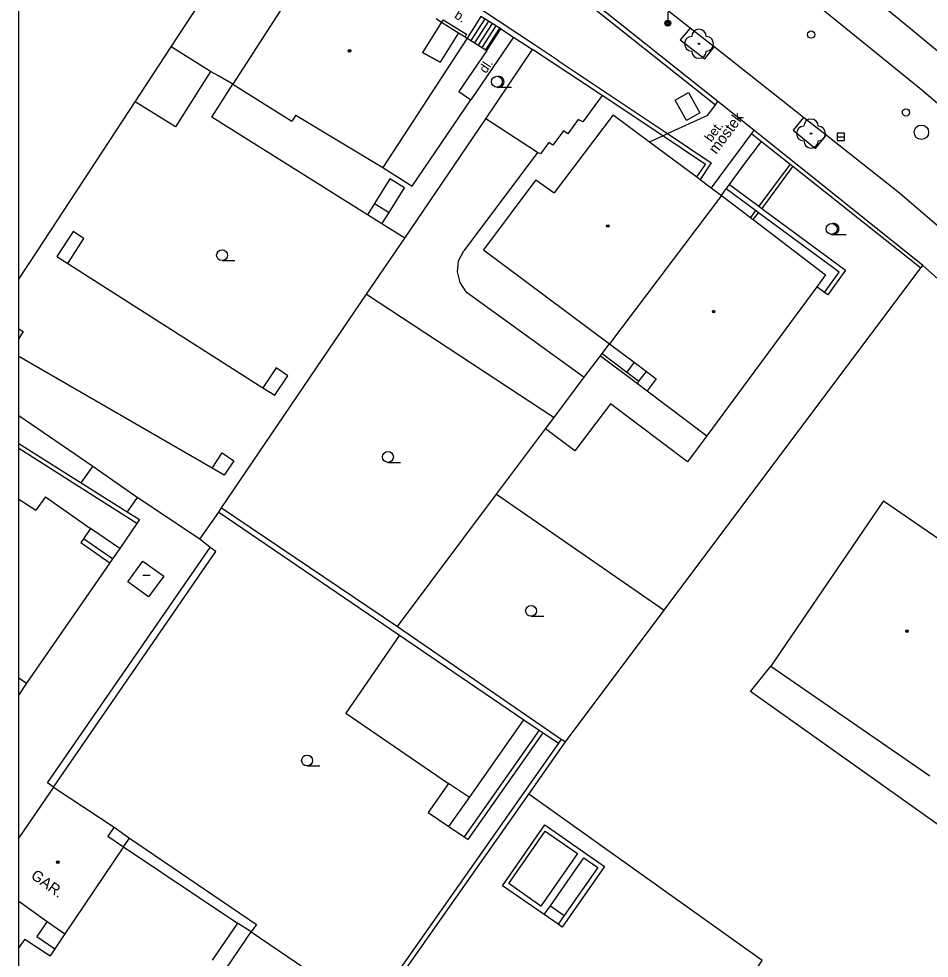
# Model space of a CAD drawing. Extents: x -600309 to -598967, y -1161267 to -1160292.
# Drawn here: x -600308.5 to -600245.8, y -1160468.4 to -1160403.6 of the extents above; entities that cross this region are included whole.
import ezdxf

# ---------------------------------------------------------------- set-up
doc = ezdxf.new("R2010")
doc.units = 0
for name, color, linetype in [('Level 10', 7, 'Continuous'), ('Level 11', 7, 'Continuous'), ('Level 22', 7, 'Continuous'), ('Level 27', 7, 'Continuous'), ('Level 28', 7, 'Continuous'), ('Level 33', 7, 'Continuous'), ('Level 36', 7, 'Continuous'), ('Level 39', 7, 'Continuous'), ('Level 40', 7, 'Continuous'), ('Level 41', 7, 'Continuous'), ('Level 5', 7, 'Continuous'), ('Level 6', 7, 'Continuous'), ('Level 7', 7, 'Continuous'), ('Level 8', 7, 'Continuous'), ('Vrstva 63', 7, 'Continuous')]:
    doc.layers.add(name, color=color, linetype=linetype)

msp = doc.modelspace()

# ---------------------------------------------------------------- linework, layer by layer
at = {"layer": 'Level 10'}
for points in [[(-600130.99, -1160509.15), (-600139.44, -1160503.56), (-600147.26, -1160498.02), (-600154.8, -1160492.15), (-600161.77, -1160486.34), (-600165.04, -1160483.54), (-600170.09, -1160478.96), (-600176.09, -1160473.27), (-600190.6599, -1160459.23), (-600212.67, -1160438.18), (-600221.71, -1160429.76), (-600228.39, -1160423.74), (-600239.15, -1160414.63), (-600244.48, -1160410.12), (-600246.35, -1160408.54), (-600258.81, -1160398.4099), (-600274.98, -1160385.83), (-600282.26, -1160380.2)], [(-600116.15, -1160526.25), (-600126.1, -1160520.21), (-600138.76, -1160511.76), (-600151.84, -1160502.25), (-600159.7, -1160496.34), (-600170.75, -1160487.14), (-600176.1, -1160482.15), (-600185.2199, -1160473.25), (-600195.18, -1160463.81), (-600206.08, -1160453.49), (-600217.54, -1160442.6), (-600229.4099, -1160431.52), (-600247.87, -1160415.6599), (-600252.92, -1160411.68), (-600254.47, -1160410.46), (-600260.64, -1160405.59), (-600262.29, -1160404.29), (-600268.29, -1160399.56)]]:
    msp.add_lwpolyline(points, dxfattribs=at)
at = {"layer": 'Level 11'}
for p, q in [((-600308.541, -1160421.6025), (-600307.25, -1160419.63)), ((-600308.541, -1160425.0133), (-600308.24, -1160425.21)), ((-600308.24, -1160425.21), (-600308.541, -1160425.6699)), ((-600295.23, -1160434.62), (-600308.541, -1160426.9111)), ((-600303.44, -1160434.5), (-600308.541, -1160431.0176)), ((-600308.541, -1160432.9066), (-600304.24, -1160435.62)), ((-600300.42, -1160438.44), (-600308.541, -1160433.2536)), ((-600308, -1160449.44), (-600308.541, -1160450.2268))]:
    msp.add_line(p, q, dxfattribs=at)
for points in [[(-600271.36, -1160406.54), (-600272.94, -1160405.48), (-600276.81, -1160402.95), (-600274.1, -1160398.77)], [(-600276.7, -1160403.5), (-600277.65, -1160404.99)], [(-600276.44, -1160403.6599), (-600277.39, -1160405.15)], [(-600276.19, -1160403.82), (-600277.14, -1160405.31)], [(-600275.94, -1160403.98), (-600276.89, -1160405.4699)], [(-600275.68, -1160404.14), (-600276.63, -1160405.63)], [(-600275.43, -1160404.3), (-600276.38, -1160405.79)], [(-600276.29, -1160405.84), (-600275.34, -1160404.35)], [(-600262.29, -1160404.29), (-600262.968, -1160405.11), (-600261.286, -1160406.398), (-600260.64, -1160405.59)], [(-600277.65, -1160404.99), (-600276.29, -1160405.84)], [(-600274.4699, -1160404.9099), (-600277.39, -1160409.23)], [(-600300.52, -1160409.37), (-600298.04, -1160405.59)], [(-600276.29, -1160405.84), (-600278.2199, -1160408.67)], [(-600276.37, -1160410.54), (-600273.14, -1160405.77)], [(-600295.33, -1160407.28), (-600297.74, -1160411.1)], [(-600293.8, -1160408.1599), (-600294.79, -1160407.59)], [(-600295.24, -1160410.43), (-600293.8, -1160408.1599)], [(-600278.22, -1160408.67), (-600277.39, -1160409.23)], [(-600262.4, -1160408.73), (-600261.63, -1160410.13), (-600262.55, -1160410.65), (-600263.33, -1160409.25), (-600262.4, -1160408.73)], [(-600307.25, -1160419.63), (-600300.52, -1160409.37)], [(-600297.74, -1160411.1), (-600300.52, -1160409.37)], [(-600283.45, -1160413.9), (-600281.43, -1160415.19), (-600277.39, -1160409.23)], [(-600268.36, -1160408.94), (-600269.69, -1160410.76), (-600270.01, -1160410.58), (-600270.71, -1160411.57), (-600271.01, -1160411.38), (-600271.76, -1160412.37), (-600272.02, -1160412.18), (-600272.61, -1160412.96), (-600272.8, -1160412.86)], [(-600265.09, -1160412.14), (-600264.18, -1160411.72), (-600263.85, -1160411.56), (-600261.07, -1160410.28), (-600260.55, -1160409.57)], [(-600284.52, -1160417.15), (-600295.24, -1160410.43)], [(-600281.95, -1160418.77), (-600276.37, -1160410.54)], [(-600272.8, -1160412.86), (-600276.37, -1160410.54)], [(-600254.47, -1160410.46), (-600255.2, -1160411.32), (-600253.647, -1160412.578), (-600252.92, -1160411.68)], [(-600258.06, -1160411.55), (-600260.84, -1160415.29)], [(-600258.58, -1160413.7199), (-600257.37, -1160412.1)], [(-600272.8, -1160412.86), (-600277.89, -1160419.64)], [(-600259.58, -1160415.08), (-600258.58, -1160413.7199)], [(-600255.21, -1160413.81), (-600257.36, -1160416.7199)], [(-600255.4099, -1160413.6599), (-600256.61, -1160415.29)], [(-600283.03, -1160417), (-600281.9699, -1160415.31), (-600282.9699, -1160414.68), (-600284.03, -1160416.37)], [(-600259.8, -1160415.37), (-600259.58, -1160415.08)], [(-600259.58, -1160415.08), (-600257.56, -1160416.57)], [(-600260.13, -1160415.82), (-600259.8, -1160415.37)], [(-600257.78, -1160416.86), (-600259.8, -1160415.37)], [(-600256.61, -1160415.29), (-600257.56, -1160416.57)], [(-600284.03, -1160416.37), (-600284.52, -1160417.15)], [(-600284.03, -1160416.37), (-600283.03, -1160417)], [(-600283.52, -1160417.78), (-600284.52, -1160417.15)], [(-600283.52, -1160417.78), (-600283.03, -1160417)], [(-600257.78, -1160416.86), (-600258.14, -1160417.34)], [(-600257.94, -1160417.49), (-600257.58, -1160417.01)], [(-600257.58, -1160417.01), (-600257.78, -1160416.86)], [(-600253.03, -1160422.51), (-600252.02, -1160421.11), (-600257.58, -1160417.01)], [(-600257.56, -1160416.57), (-600257.36, -1160416.7199)], [(-600257.36, -1160416.7199), (-600251.58, -1160420.98), (-600252.8, -1160422.67), (-600253.03, -1160422.51)], [(-600281.95, -1160418.77), (-600283.52, -1160417.78)], [(-600304.79, -1160418.31), (-600305.92, -1160420.03)], [(-600304.05, -1160418.8), (-600304.79, -1160418.31)], [(-600305.1599, -1160420.51), (-600304.05, -1160418.8)], [(-600284.59, -1160422.62), (-600281.95, -1160418.77)], [(-600277.71, -1160422.4699), (-600278.14, -1160421.83), (-600278.32, -1160421.09), (-600278.24, -1160420.33), (-600277.89, -1160419.64)], [(-600305.92, -1160420.03), (-600305.1599, -1160420.51)], [(-600305.1599, -1160420.51), (-600291.7199, -1160429.07)], [(-600264.08, -1160444.4), (-600246.39, -1160420.82)], [(-600212.28, -1160451.76), (-600219, -1160445.31), (-600230.46, -1160434.68), (-600246.25, -1160420.64)], [(-600253.03, -1160422.51), (-600253.56, -1160422.13)], [(-600294.57, -1160437.35), (-600284.59, -1160422.62)], [(-600284.59, -1160422.62), (-600271.6599, -1160431.12)], [(-600277.71, -1160422.4699), (-600269.59, -1160428.35)], [(-600268.36, -1160426.7199), (-600267.84, -1160426.04)], [(-600269.59, -1160428.35), (-600268.4699, -1160426.87)], [(-600268.4699, -1160426.87), (-600268.36, -1160426.7199)], [(-600268.4699, -1160426.87), (-600265.92, -1160428.78)], [(-600268.36, -1160426.7199), (-600266.65, -1160428.01)], [(-600266.14, -1160427.32), (-600266.65, -1160428.01)], [(-600290.81, -1160427.71), (-600291.7199, -1160429.07)], [(-600290.01, -1160428.25), (-600290.81, -1160427.71)], [(-600266.65, -1160428.01), (-600265.82, -1160428.63)], [(-600265.82, -1160428.63), (-600265.3, -1160427.95)], [(-600290.9099, -1160429.58), (-600290.01, -1160428.25)], [(-600271.6599, -1160431.12), (-600269.59, -1160428.35)], [(-600265.82, -1160428.63), (-600265.92, -1160428.78)], [(-600265.92, -1160428.78), (-600265.24, -1160429.29)], [(-600291.7199, -1160429.07), (-600290.9099, -1160429.58)], [(-600261.13, -1160432.38), (-600262.48, -1160434.17), (-600267.78, -1160430.19), (-600270.23, -1160433.43), (-600272.25, -1160431.9)], [(-600272.25, -1160431.9), (-600271.6599, -1160431.12)], [(-600275.62, -1160436.4099), (-600272.25, -1160431.9)], [(-600295.23, -1160434.62), (-600294.52, -1160433.57)], [(-600294.52, -1160433.57), (-600293.73, -1160434.11)], [(-600304.24, -1160435.62), (-600303.44, -1160434.5)], [(-600300.39, -1160436.64), (-600303.44, -1160434.5)], [(-600294.4, -1160435.1), (-600295.23, -1160434.62)], [(-600293.73, -1160434.11), (-600294.4, -1160435.1)], [(-600304.24, -1160435.62), (-600301.07, -1160437.62)], [(-600282.45, -1160445.53), (-600275.62, -1160436.4099)], [(-600275.62, -1160436.4099), (-600264.08, -1160444.4)], [(-600300.39, -1160436.64), (-600301.07, -1160437.62)], [(-600296.07, -1160439.52), (-600300.39, -1160436.64)], [(-600301.07, -1160437.62), (-600300.2199, -1160438.1599)], [(-600296.07, -1160439.52), (-600294.77, -1160437.64)], [(-600300.42, -1160438.44), (-600301.59, -1160440.15)], [(-600300.2199, -1160438.1599), (-600300.42, -1160438.44)], [(-600301.59, -1160440.15), (-600303.6, -1160438.77)], [(-600302.08, -1160440.86), (-600304.09, -1160439.48)], [(-600295.36, -1160440.08), (-600296.07, -1160439.52)], [(-600306.14, -1160456.6), (-600306.57, -1160456.3), (-600295.36, -1160440.08)], [(-600306.14, -1160456.6), (-600294.96, -1160440.36), (-600295.36, -1160440.08)], [(-600301.59, -1160440.15), (-600302.08, -1160440.86)], [(-600302.08, -1160440.86), (-600302.27, -1160441.13)], [(-600270.88, -1160453.48), (-600264.08, -1160444.4)], [(-600282.31, -1160446.12), (-600286.02, -1160451.51), (-600278.93, -1160456.34)], [(-600234.53, -1160468.07), (-600234.82, -1160466.5), (-600236.08, -1160465.67), (-600258.13, -1160450), (-600256.73, -1160448.27)], [(-600277.5, -1160457.31), (-600273.74, -1160451.95)], [(-600272.68, -1160452.67), (-600277.86, -1160460.03)], [(-600277.86, -1160460.03), (-600277.59, -1160460.21), (-600272.42, -1160452.85)], [(-600278.93, -1160456.34), (-600280.34, -1160458.35), (-600278.9099, -1160459.32)], [(-600277.5, -1160457.31), (-600278.93, -1160456.34)], [(-600278.9099, -1160459.32), (-600277.5, -1160457.31)], [(-600266.04, -1160481.38), (-600257.33, -1160468.55), (-600273.4, -1160457.09)], [(-600272.34, -1160465.38), (-600275.2199, -1160463.39), (-600272.31, -1160459.2), (-600268.19, -1160462.06), (-600271.1, -1160466.25), (-600271.38, -1160466.05)], [(-600301.98, -1160459.36), (-600300.92, -1160460.12)], [(-600278.9099, -1160459.32), (-600277.86, -1160460.03)], [(-600272.28, -1160459.63), (-600270.05, -1160461.17), (-600272.57, -1160464.79), (-600274.79, -1160463.24), (-600272.28, -1160459.63)], [(-600301.32, -1160460.7), (-600300.92, -1160460.12)], [(-600300.92, -1160460.12), (-600292.17, -1160466.07)], [(-600271.92, -1160464.78), (-600269.62, -1160461.4699), (-600268.6599, -1160462.14), (-600270.96, -1160465.45)], [(-600272.34, -1160465.38), (-600271.92, -1160464.78)], [(-600271.92, -1160464.78), (-600270.96, -1160465.45)], [(-600271.38, -1160466.05), (-600272.34, -1160465.38)], [(-600270.96, -1160465.45), (-600271.38, -1160466.05)], [(-600306.59, -1160465.85), (-600307.29, -1160466.89)], [(-600292.53, -1160466.57), (-600293.48, -1160465.96)], [(-600292.17, -1160466.07), (-600292.53, -1160466.57)], [(-600307.29, -1160466.89), (-600306.05, -1160467.74)], [(-600294.27, -1160469.15), (-600292.53, -1160466.57)], [(-600292.53, -1160466.57), (-600284.39, -1160472.1)]]:
    msp.add_lwpolyline(points, dxfattribs=at)
at = {"layer": 'Level 22'}
for centre in [(-600261.68, -1160405.37), (-600253.96, -1160411.56)]:
    msp.add_circle(centre, 0.05, dxfattribs=at)
for centre, start, end in [((-600262.18, -1160405.37), 90, 270), ((-600261.68, -1160404.87), 0, 180), ((-600261.18, -1160405.37), 270, 90), ((-600261.68, -1160405.87), 180, 0), ((-600253.96, -1160411.06), 0, 180), ((-600254.46, -1160411.56), 90, 270), ((-600253.46, -1160411.56), 270, 90), ((-600253.96, -1160412.06), 180, 0)]:
    msp.add_arc(centre, 0.5, start, end, dxfattribs=at)
at = {"layer": 'Level 27'}
msp.add_line((-600252.15, -1160411.79), (-600251.65, -1160411.79), dxfattribs=at)
msp.add_lwpolyline([(-600252.15, -1160412.04), (-600251.65, -1160412.04), (-600251.65, -1160411.54), (-600252.15, -1160411.54)], close=True, dxfattribs=at)
msp.add_circle((-600246.36, -1160411.4699), 0.5, dxfattribs=at)
at = {"layer": 'Level 28'}
for centre in [(-600253.95, -1160404.74), (-600247.42, -1160410.1)]:
    msp.add_circle(centre, 0.25, dxfattribs=at)
at = {"layer": 'Level 33'}
msp.add_line((-600263.83, -1160403.2), (-600263.83, -1160403.95), dxfattribs=at)
for radius in [0.2, 0.1445, 0.0876]:
    msp.add_circle((-600263.83, -1160403.95), radius, dxfattribs=at)
at = {"layer": 'Level 36'}
for p, q in [((-600275.6, -1160408.365), (-600274.6, -1160408.365)), ((-600252.54, -1160418.505), (-600251.54, -1160418.505)), ((-600294.54, -1160420.315), (-600293.665, -1160420.315)), ((-600283.11, -1160434.215), (-600282.235, -1160434.215)), ((-600273.25, -1160444.825), (-600272.375, -1160444.825)), ((-600288.68, -1160455.135), (-600287.805, -1160455.135))]:
    msp.add_line(p, q, dxfattribs=at)
for centre in [(-600275.6, -1160407.9896), (-600252.54, -1160418.1296), (-600294.5401, -1160419.9399), (-600283.1101, -1160433.8399), (-600273.2501, -1160444.4499), (-600288.6801, -1160454.7599)]:
    msp.add_circle(centre, 0.375, dxfattribs=at)
for centre in [(-600275.475, -1160407.9896), (-600252.415, -1160418.1296)]:
    msp.add_arc(centre, 0.375, 260.405931, 99.594069, dxfattribs=at)
at = {"layer": 'Level 39'}
msp.add_line((-600300, -1160442), (-600299.5, -1160442), dxfattribs=at)
for centre, radius in [((-600285.75, -1160405.86), 0.09), ((-600285.75, -1160405.86), 0.0398), ((-600267.96, -1160417.93), 0.09), ((-600267.96, -1160417.93), 0.0398), ((-600260.67, -1160423.83), 0.09), ((-600260.67, -1160423.83), 0.0398), ((-600247.35, -1160445.85), 0.09), ((-600247.35, -1160445.85), 0.0398), ((-600305.86, -1160461.77), 0.09), ((-600305.86, -1160461.77), 0.0398)]:
    msp.add_circle(centre, radius, dxfattribs=at)
at = {"layer": 'Level 5'}
for p, q in [((-600308.541, -1160436.7493), (-600307.36, -1160437.5)), ((-600308.541, -1160449.0671), (-600308, -1160449.44)), ((-600306.14, -1160456.6), (-600308.541, -1160460.0844)), ((-600308.541, -1160464.447), (-600306.59, -1160465.85)), ((-600308.13, -1160467.08), (-600308.541, -1160467.6479))]:
    msp.add_line(p, q, dxfattribs=at)
for points in [[(-600290.28, -1160402.7199), (-600293.8, -1160408.1599)], [(-600279.4099, -1160403.88), (-600280.73, -1160405.9699)], [(-600279.78, -1160403.64), (-600279.4099, -1160403.88)], [(-600279.31, -1160403.7199), (-600279.4099, -1160403.88)], [(-600279.4099, -1160403.88), (-600278.24, -1160404.62)], [(-600279.31, -1160403.7199), (-600277.69, -1160404.7199)], [(-600278.24, -1160404.62), (-600279.51, -1160406.64)], [(-600278.24, -1160404.62), (-600277.8, -1160404.89)], [(-600277.69, -1160404.7199), (-600277.8, -1160404.89)], [(-600277.8, -1160404.89), (-600277.65, -1160404.99)], [(-600277.65, -1160404.99), (-600283.45, -1160413.9)], [(-600280.73, -1160405.9699), (-600279.51, -1160406.64)], [(-600293.8, -1160408.1599), (-600289.7199, -1160410.7)], [(-600289.46, -1160410.3), (-600289.7199, -1160410.7)], [(-600289.46, -1160410.3), (-600283.45, -1160413.9)], [(-600267.6, -1160410.27), (-600271.65, -1160415.64)], [(-600267.6, -1160410.27), (-600265.09, -1160412.14), (-600261.84, -1160414.55)], [(-600261.84, -1160414.55), (-600261.6, -1160414.73)], [(-600272.9099, -1160414.74), (-600276.52, -1160419.58)], [(-600272.9099, -1160414.74), (-600271.65, -1160415.64)], [(-600261.6, -1160414.73), (-600260.84, -1160415.29), (-600260.13, -1160415.82)], [(-600260.13, -1160415.82), (-600267.84, -1160426.04)], [(-600260.13, -1160415.82), (-600258.14, -1160417.34)], [(-600258.14, -1160417.34), (-600257.94, -1160417.49)], [(-600257.94, -1160417.49), (-600252.96, -1160421.3)], [(-600276.52, -1160419.58), (-600267.84, -1160426.04)], [(-600252.96, -1160421.3), (-600253.56, -1160422.13)], [(-600253.56, -1160422.13), (-600261.13, -1160432.38)], [(-600267.84, -1160426.04), (-600266.14, -1160427.32)], [(-600266.14, -1160427.32), (-600265.3, -1160427.95)], [(-600265.3, -1160427.95), (-600264.62, -1160428.46)], [(-600264.62, -1160428.46), (-600265.24, -1160429.29)], [(-600265.24, -1160429.29), (-600261.13, -1160432.38)], [(-600306.71, -1160436.6), (-600307.36, -1160437.5)], [(-600306.71, -1160436.6), (-600303.6, -1160438.77)], [(-600248.96, -1160436.86), (-600256.73, -1160448.27)], [(-600248.96, -1160436.86), (-600237.9699, -1160444.42)], [(-600303.6, -1160438.77), (-600304.09, -1160439.48)], [(-600304.09, -1160439.48), (-600304.27, -1160439.75)], [(-600304.27, -1160439.75), (-600302.27, -1160441.13)], [(-600302.27, -1160441.13), (-600308, -1160449.44)], [(-600301.03, -1160442.45), (-600299.99, -1160441.02)], [(-600299.99, -1160441.02), (-600298.56, -1160442.07)], [(-600298.56, -1160442.07), (-600299.61, -1160443.49)], [(-600299.61, -1160443.49), (-600301.03, -1160442.45)], [(-600256.73, -1160448.27), (-600245.78, -1160455.81)], [(-600306.14, -1160456.6), (-600301.98, -1160459.36)], [(-600301.98, -1160459.36), (-600302.4, -1160459.98)], [(-600302.4, -1160459.98), (-600301.32, -1160460.7)], [(-600301.32, -1160460.7), (-600305.37, -1160466.71)], [(-600301.32, -1160460.7), (-600293.48, -1160465.96)], [(-600306.59, -1160465.85), (-600305.37, -1160466.71)], [(-600293.48, -1160465.96), (-600295.2199, -1160468.51)], [(-600305.37, -1160466.71), (-600306.05, -1160467.74)], [(-600308.13, -1160467.08), (-600306.39, -1160468.2199)], [(-600306.05, -1160467.74), (-600306.39, -1160468.2199)]]:
    msp.add_lwpolyline(points, dxfattribs=at)
at = {"layer": 'Level 6'}
msp.add_lwpolyline([(-600279.51, -1160406.64), (-600280.73, -1160405.9699)], dxfattribs=at)
at = {"layer": 'Level 7'}
for points in [[(-600298.04, -1160405.59), (-600290.84, -1160394.59)], [(-600260.55, -1160409.57), (-600260.39, -1160409.35), (-600270.26, -1160401.4699)], [(-600270.45, -1160401.7), (-600260.55, -1160409.57)], [(-600275.34, -1160404.35), (-600276.7, -1160403.5)], [(-600275.34, -1160404.35), (-600274.4699, -1160404.9099)], [(-600274.4699, -1160404.9099), (-600273.14, -1160405.77)], [(-600295.33, -1160407.28), (-600298.04, -1160405.59)], [(-600268.36, -1160408.94), (-600273.14, -1160405.77)], [(-600271.36, -1160406.54), (-600263.85, -1160411.56)], [(-600294.79, -1160407.59), (-600295.33, -1160407.28)], [(-600264.18, -1160411.72), (-600268.36, -1160408.94)], [(-600257.21, -1160411.88), (-600257.9, -1160411.33), (-600258.06, -1160411.55)], [(-600261.84, -1160414.55), (-600261.23, -1160413.68), (-600264.18, -1160411.72)], [(-600263.85, -1160411.56), (-600260.83, -1160413.58), (-600261.6, -1160414.73)], [(-600258.06, -1160411.55), (-600257.37, -1160412.1)], [(-600246.25, -1160420.64), (-600257.21, -1160411.88)], [(-600257.37, -1160412.1), (-600255.4099, -1160413.6599)], [(-600255.4099, -1160413.6599), (-600255.21, -1160413.81)], [(-600255.21, -1160413.81), (-600246.39, -1160420.82)], [(-600246.39, -1160420.82), (-600246.25, -1160420.64)], [(-600294.77, -1160437.64), (-600294.57, -1160437.35)], [(-600294.77, -1160437.64), (-600282.31, -1160446.12)], [(-600294.57, -1160437.35), (-600282.45, -1160445.53)], [(-600282.45, -1160445.53), (-600271.17, -1160453.28)], [(-600282.31, -1160446.12), (-600273.74, -1160451.95)], [(-600273.74, -1160451.95), (-600272.68, -1160452.67)], [(-600272.68, -1160452.67), (-600272.42, -1160452.85)], [(-600272.42, -1160452.85), (-600271.37, -1160453.57)], [(-600271.17, -1160453.28), (-600271.37, -1160453.57)], [(-600271.17, -1160453.28), (-600270.88, -1160453.48)], [(-600271.37, -1160453.57), (-600284.39, -1160472.1)], [(-600273.4, -1160457.09), (-600270.88, -1160453.48)], [(-600282.81, -1160470.4699), (-600273.4, -1160457.09)]]:
    msp.add_lwpolyline(points, dxfattribs=at)
at = {"layer": 'Level 8'}
for points in [[(-600244.73, -1160406.31), (-600245, -1160406.09), (-600247.25, -1160404.22), (-600250.43, -1160401.59)], [(-600257.9, -1160411.33), (-600260.39, -1160409.35)]]:
    msp.add_lwpolyline(points, dxfattribs=at)
at = {"layer": 'Vrstva 63'}
msp.add_lwpolyline([(-600308.541, -1160292.3474), (-598967.1085, -1160292.3474), (-598967.1085, -1161267.0314), (-600308.541, -1161267.0314)], close=True, dxfattribs=at)

# ---------------------------------------------------------------- texts
at = {"layer": 'Level 40'}
for s, rotation, p in [('b.', 328.37, (-600278.59, -1160403.56)), ('dl.', 55.88, (-600276.35, -1160407.46)), ('dl.', 55.882292, (-600276.35, -1160407.46)), ('bet.', 53.426969, (-600260.84, -1160412.19))]:
    msp.add_text(s, height=0.65, rotation=rotation, dxfattribs=at).set_placement(p)
at = {"layer": 'Level 41'}
for s, rotation, p in [('mostek', 53.426969, (-600260.49, -1160413.03)), ('GAR.', 324, (-600307.77, -1160462.82))]:
    msp.add_text(s, height=0.75, rotation=rotation, dxfattribs=at).set_placement(p)

doc.saveas('drawing.dxf')
